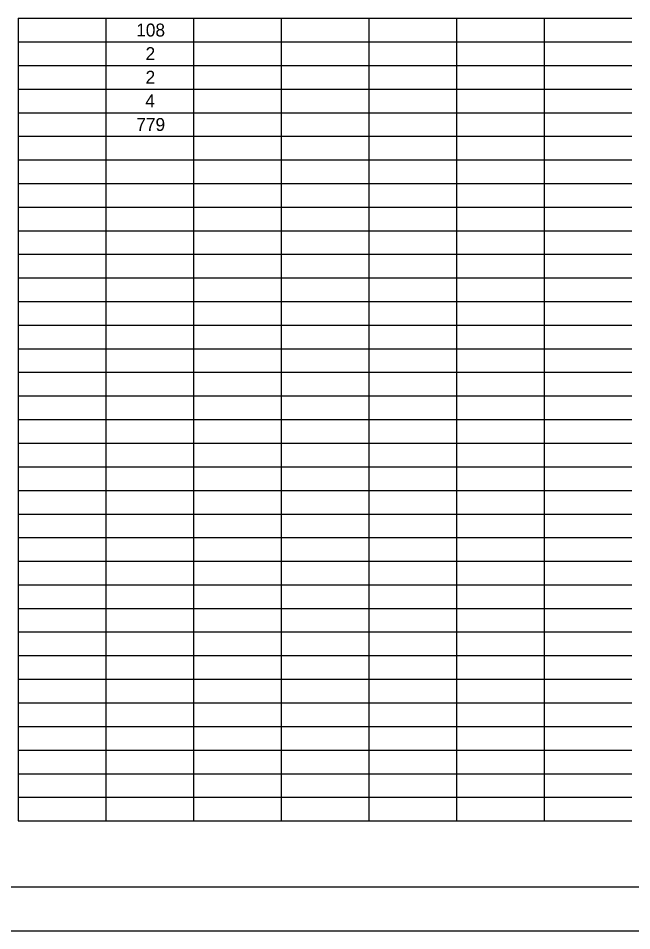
# Model space of a CAD drawing. Extents: x 0 to 34, y 0 to 22.
# Drawn here: x 8.52 to 15.54, y 0 to 10.43 of the extents above; entities that cross this region are included whole.
import ezdxf

# ---------------------------------------------------------------- set-up
doc = ezdxf.new("R2010")
doc.units = 0
for name, color, linetype in [('SH_Border', 7, 'Continuous'), ('SH_Cut_Line', 7, 'Continuous'), ('SH_Text', 7, 'Continuous')]:
    doc.layers.add(name, color=color, linetype=linetype)

msp = doc.modelspace()

# ---------------------------------------------------------------- linework, layer by layer
at = {"layer": 'SH_Border'}
msp.add_lwpolyline([(1.5, 21.5), (33.5, 21.5), (33.5, 0.5), (1.5, 0.5)], close=True, dxfattribs=at)
at = {"layer": 'SH_Cut_Line'}
msp.add_lwpolyline([(0, 0), (34, 0), (34, 22), (0, 22)], close=True, dxfattribs=at)
at = {"layer": 'SH_Text'}
for p, q in [((8.518, 10.434), (9.52, 10.434)), ((8.518, 10.434), (8.518, 10.164)), ((9.52, 10.434), (11.525, 10.434)), ((9.52, 10.434), (9.52, 10.164)), ((10.523, 10.434), (10.523, 10.164)), ((11.525, 10.434), (12.528, 10.434)), ((11.525, 10.434), (11.525, 10.164)), ((12.528, 10.434), (13.53, 10.434)), ((12.528, 10.434), (12.528, 10.164)), ((13.53, 10.434), (14.533, 10.434)), ((13.53, 10.434), (13.53, 10.164)), ((14.533, 10.434), (15.535, 10.434)), ((14.533, 10.434), (14.533, 10.164)), ((8.518, 10.164), (9.52, 10.164)), ((8.518, 10.164), (8.518, 9.354)), ((9.52, 10.164), (11.525, 10.164)), ((9.52, 10.164), (9.52, 9.354)), ((10.523, 10.164), (10.523, 9.354)), ((11.525, 10.164), (12.528, 10.164)), ((11.525, 10.164), (11.525, 9.354)), ((12.528, 10.164), (13.53, 10.164)), ((12.528, 10.164), (12.528, 9.354)), ((13.53, 10.164), (14.533, 10.164)), ((13.53, 10.164), (13.53, 9.354)), ((14.533, 10.164), (15.535, 10.164)), ((14.533, 10.164), (14.533, 9.354)), ((8.518, 9.894), (9.52, 9.894)), ((9.52, 9.894), (11.525, 9.894)), ((11.525, 9.894), (12.528, 9.894)), ((12.528, 9.894), (13.53, 9.894)), ((13.53, 9.894), (14.533, 9.894)), ((14.533, 9.894), (15.535, 9.894)), ((8.518, 9.624), (9.52, 9.624)), ((9.52, 9.624), (11.525, 9.624)), ((11.525, 9.624), (12.528, 9.624)), ((12.528, 9.624), (13.53, 9.624)), ((13.53, 9.624), (14.533, 9.624)), ((14.533, 9.624), (15.535, 9.624)), ((8.518, 9.354), (9.52, 9.354)), ((8.518, 9.354), (8.518, 8.814)), ((9.52, 9.354), (11.525, 9.354)), ((9.52, 9.354), (9.52, 8.814)), ((10.523, 9.354), (10.523, 8.814)), ((11.525, 9.354), (12.528, 9.354)), ((11.525, 9.354), (11.525, 8.814)), ((12.528, 9.354), (13.53, 9.354)), ((12.528, 9.354), (12.528, 8.814)), ((13.53, 9.354), (14.533, 9.354)), ((13.53, 9.354), (13.53, 8.814)), ((14.533, 9.354), (15.535, 9.354)), ((14.533, 9.354), (14.533, 8.814)), ((8.518, 9.084), (9.52, 9.084)), ((9.52, 9.084), (11.525, 9.084)), ((11.525, 9.084), (12.528, 9.084)), ((12.528, 9.084), (13.53, 9.084)), ((13.53, 9.084), (14.533, 9.084)), ((14.533, 9.084), (15.535, 9.084)), ((8.518, 8.814), (9.52, 8.814)), ((8.518, 8.814), (8.518, 8.004)), ((9.52, 8.814), (11.525, 8.814)), ((9.52, 8.814), (9.52, 8.004)), ((10.523, 8.814), (10.523, 8.004)), ((11.525, 8.814), (12.528, 8.814)), ((11.525, 8.814), (11.525, 8.004)), ((12.528, 8.814), (13.53, 8.814)), ((12.528, 8.814), (12.528, 8.004)), ((13.53, 8.814), (14.533, 8.814)), ((13.53, 8.814), (13.53, 8.004)), ((14.533, 8.814), (15.535, 8.814)), ((14.533, 8.814), (14.533, 8.004)), ((8.518, 8.544), (9.52, 8.544)), ((9.52, 8.544), (11.525, 8.544)), ((11.525, 8.544), (12.528, 8.544)), ((12.528, 8.544), (13.53, 8.544)), ((13.53, 8.544), (14.533, 8.544)), ((14.533, 8.544), (15.535, 8.544)), ((8.518, 8.274), (9.52, 8.274)), ((9.52, 8.274), (11.525, 8.274)), ((11.525, 8.274), (12.528, 8.274)), ((12.528, 8.274), (13.53, 8.274)), ((13.53, 8.274), (14.533, 8.274)), ((14.533, 8.274), (15.535, 8.274)), ((8.518, 8.004), (9.52, 8.004)), ((8.518, 8.004), (8.518, 7.465)), ((9.52, 8.004), (11.525, 8.004)), ((9.52, 8.004), (9.52, 7.465)), ((10.523, 8.004), (10.523, 7.465)), ((11.525, 8.004), (12.528, 8.004)), ((11.525, 8.004), (11.525, 7.465)), ((12.528, 8.004), (13.53, 8.004)), ((12.528, 8.004), (12.528, 7.465)), ((13.53, 8.004), (14.533, 8.004)), ((13.53, 8.004), (13.53, 7.465)), ((14.533, 8.004), (15.535, 8.004)), ((14.533, 8.004), (14.533, 7.465)), ((8.518, 7.735), (9.52, 7.735)), ((9.52, 7.735), (11.525, 7.735)), ((11.525, 7.735), (12.528, 7.735)), ((12.528, 7.735), (13.53, 7.735)), ((13.53, 7.735), (14.533, 7.735)), ((14.533, 7.735), (15.535, 7.735)), ((8.518, 7.465), (9.52, 7.465)), ((8.518, 7.465), (8.518, 6.655)), ((9.52, 7.465), (11.525, 7.465)), ((9.52, 7.465), (9.52, 6.655)), ((10.523, 7.465), (10.523, 6.655)), ((11.525, 7.465), (12.528, 7.465)), ((11.525, 7.465), (11.525, 6.655)), ((12.528, 7.465), (13.53, 7.465)), ((12.528, 7.465), (12.528, 6.655)), ((13.53, 7.465), (14.533, 7.465)), ((13.53, 7.465), (13.53, 6.655)), ((14.533, 7.465), (15.535, 7.465)), ((14.533, 7.465), (14.533, 6.655)), ((8.518, 7.195), (9.52, 7.195)), ((9.52, 7.195), (11.525, 7.195)), ((11.525, 7.195), (12.528, 7.195)), ((12.528, 7.195), (13.53, 7.195)), ((13.53, 7.195), (14.533, 7.195)), ((14.533, 7.195), (15.535, 7.195)), ((8.518, 6.925), (9.52, 6.925)), ((9.52, 6.925), (11.525, 6.925)), ((11.525, 6.925), (12.528, 6.925)), ((12.528, 6.925), (13.53, 6.925)), ((13.53, 6.925), (14.533, 6.925)), ((14.533, 6.925), (15.535, 6.925)), ((8.518, 6.655), (9.52, 6.655)), ((8.518, 6.655), (8.518, 5.575)), ((9.52, 6.655), (11.525, 6.655)), ((9.52, 6.655), (9.52, 5.575)), ((10.523, 6.655), (10.523, 5.575)), ((11.525, 6.655), (12.528, 6.655)), ((11.525, 6.655), (11.525, 5.575)), ((12.528, 6.655), (13.53, 6.655)), ((12.528, 6.655), (12.528, 5.575)), ((13.53, 6.655), (14.533, 6.655)), ((13.53, 6.655), (13.53, 5.575)), ((14.533, 6.655), (15.535, 6.655)), ((14.533, 6.655), (14.533, 5.575)), ((8.518, 6.385), (9.52, 6.385)), ((9.52, 6.385), (11.525, 6.385)), ((11.525, 6.385), (12.528, 6.385)), ((12.528, 6.385), (13.53, 6.385)), ((13.53, 6.385), (14.533, 6.385)), ((14.533, 6.385), (15.535, 6.385)), ((8.518, 6.115), (9.52, 6.115)), ((9.52, 6.115), (11.525, 6.115)), ((11.525, 6.115), (12.528, 6.115)), ((12.528, 6.115), (13.53, 6.115)), ((13.53, 6.115), (14.533, 6.115)), ((14.533, 6.115), (15.535, 6.115)), ((8.518, 5.845), (9.52, 5.845)), ((9.52, 5.845), (11.525, 5.845)), ((11.525, 5.845), (12.528, 5.845)), ((12.528, 5.845), (13.53, 5.845)), ((13.53, 5.845), (14.533, 5.845)), ((14.533, 5.845), (15.535, 5.845)), ((8.518, 5.575), (9.52, 5.575)), ((8.518, 5.575), (8.518, 5.305)), ((9.52, 5.575), (11.525, 5.575)), ((9.52, 5.575), (9.52, 5.305)), ((10.523, 5.575), (10.523, 5.305)), ((11.525, 5.575), (12.528, 5.575)), ((11.525, 5.575), (11.525, 5.305)), ((12.528, 5.575), (13.53, 5.575)), ((12.528, 5.575), (12.528, 5.305)), ((13.53, 5.575), (14.533, 5.575)), ((13.53, 5.575), (13.53, 5.305)), ((14.533, 5.575), (15.535, 5.575)), ((14.533, 5.575), (14.533, 5.305)), ((8.518, 5.305), (9.52, 5.305)), ((8.518, 5.305), (8.518, 4.226)), ((9.52, 5.305), (11.525, 5.305)), ((9.52, 5.305), (9.52, 4.226)), ((10.523, 5.305), (10.523, 4.226)), ((11.525, 5.305), (12.528, 5.305)), ((11.525, 5.305), (11.525, 4.226)), ((12.528, 5.305), (13.53, 5.305)), ((12.528, 5.305), (12.528, 4.226)), ((13.53, 5.305), (14.533, 5.305)), ((13.53, 5.305), (13.53, 4.226)), ((14.533, 5.305), (15.535, 5.305)), ((14.533, 5.305), (14.533, 4.226)), ((8.518, 5.035), (9.52, 5.035)), ((9.52, 5.035), (11.525, 5.035)), ((11.525, 5.035), (12.528, 5.035)), ((12.528, 5.035), (13.53, 5.035)), ((13.53, 5.035), (14.533, 5.035)), ((14.533, 5.035), (15.535, 5.035)), ((8.518, 4.765), (9.52, 4.765)), ((9.52, 4.765), (11.525, 4.765)), ((11.525, 4.765), (12.528, 4.765)), ((12.528, 4.765), (13.53, 4.765)), ((13.53, 4.765), (14.533, 4.765)), ((14.533, 4.765), (15.535, 4.765)), ((8.518, 4.496), (9.52, 4.496)), ((9.52, 4.496), (11.525, 4.496)), ((11.525, 4.496), (12.528, 4.496)), ((12.528, 4.496), (13.53, 4.496)), ((13.53, 4.496), (14.533, 4.496)), ((14.533, 4.496), (15.535, 4.496)), ((8.518, 4.226), (9.52, 4.226)), ((8.518, 4.226), (8.518, 3.956)), ((9.52, 4.226), (11.525, 4.226)), ((9.52, 4.226), (9.52, 3.956)), ((10.523, 4.226), (10.523, 3.956)), ((11.525, 4.226), (12.528, 4.226)), ((11.525, 4.226), (11.525, 3.956)), ((12.528, 4.226), (13.53, 4.226)), ((12.528, 4.226), (12.528, 3.956)), ((13.53, 4.226), (14.533, 4.226)), ((13.53, 4.226), (13.53, 3.956)), ((14.533, 4.226), (15.535, 4.226)), ((14.533, 4.226), (14.533, 3.956)), ((8.518, 3.956), (9.52, 3.956)), ((8.518, 3.956), (8.518, 2.876)), ((9.52, 3.956), (11.525, 3.956)), ((9.52, 3.956), (9.52, 2.876)), ((10.523, 3.956), (10.523, 2.876)), ((11.525, 3.956), (12.528, 3.956)), ((11.525, 3.956), (11.525, 2.876)), ((12.528, 3.956), (13.53, 3.956)), ((12.528, 3.956), (12.528, 2.876)), ((13.53, 3.956), (14.533, 3.956)), ((13.53, 3.956), (13.53, 2.876)), ((14.533, 3.956), (15.535, 3.956)), ((14.533, 3.956), (14.533, 2.876)), ((8.518, 3.686), (9.52, 3.686)), ((9.52, 3.686), (11.525, 3.686)), ((11.525, 3.686), (12.528, 3.686)), ((12.528, 3.686), (13.53, 3.686)), ((13.53, 3.686), (14.533, 3.686)), ((14.533, 3.686), (15.535, 3.686)), ((8.518, 3.416), (9.52, 3.416)), ((9.52, 3.416), (11.525, 3.416)), ((11.525, 3.416), (12.528, 3.416)), ((12.528, 3.416), (13.53, 3.416)), ((13.53, 3.416), (14.533, 3.416)), ((14.533, 3.416), (15.535, 3.416)), ((8.518, 3.146), (9.52, 3.146)), ((9.52, 3.146), (11.525, 3.146)), ((11.525, 3.146), (12.528, 3.146)), ((12.528, 3.146), (13.53, 3.146)), ((13.53, 3.146), (14.533, 3.146)), ((14.533, 3.146), (15.535, 3.146)), ((8.518, 2.876), (9.52, 2.876)), ((8.518, 2.876), (8.518, 2.606)), ((9.52, 2.876), (11.525, 2.876)), ((9.52, 2.876), (9.52, 2.606)), ((10.523, 2.876), (10.523, 2.606)), ((11.525, 2.876), (12.528, 2.876)), ((11.525, 2.876), (11.525, 2.606)), ((12.528, 2.876), (13.53, 2.876)), ((12.528, 2.876), (12.528, 2.606)), ((13.53, 2.876), (14.533, 2.876)), ((13.53, 2.876), (13.53, 2.606)), ((14.533, 2.876), (15.535, 2.876)), ((14.533, 2.876), (14.533, 2.606)), ((8.518, 2.606), (9.52, 2.606)), ((8.518, 2.606), (8.518, 1.527)), ((9.52, 2.606), (11.525, 2.606)), ((9.52, 2.606), (9.52, 1.527)), ((10.523, 2.606), (10.523, 1.527)), ((11.525, 2.606), (12.528, 2.606)), ((11.525, 2.606), (11.525, 1.527)), ((12.528, 2.606), (13.53, 2.606)), ((12.528, 2.606), (12.528, 1.527)), ((13.53, 2.606), (14.533, 2.606)), ((13.53, 2.606), (13.53, 1.527)), ((14.533, 2.606), (15.535, 2.606)), ((14.533, 2.606), (14.533, 1.527)), ((8.518, 2.336), (9.52, 2.336)), ((9.52, 2.336), (11.525, 2.336)), ((11.525, 2.336), (12.528, 2.336)), ((12.528, 2.336), (13.53, 2.336)), ((13.53, 2.336), (14.533, 2.336)), ((14.533, 2.336), (15.535, 2.336)), ((8.518, 2.066), (9.52, 2.066)), ((9.52, 2.066), (11.525, 2.066)), ((11.525, 2.066), (12.528, 2.066)), ((12.528, 2.066), (13.53, 2.066)), ((13.53, 2.066), (14.533, 2.066)), ((14.533, 2.066), (15.535, 2.066)), ((8.518, 1.796), (9.52, 1.796)), ((9.52, 1.796), (11.525, 1.796)), ((11.525, 1.796), (12.528, 1.796)), ((12.528, 1.796), (13.53, 1.796)), ((13.53, 1.796), (14.533, 1.796)), ((14.533, 1.796), (15.535, 1.796)), ((8.518, 1.527), (9.52, 1.527)), ((8.518, 1.527), (8.518, 1.257)), ((9.52, 1.527), (11.525, 1.527)), ((9.52, 1.527), (9.52, 1.257)), ((10.523, 1.527), (10.523, 1.257)), ((11.525, 1.527), (12.528, 1.527)), ((11.525, 1.527), (11.525, 1.257)), ((12.528, 1.527), (13.53, 1.527)), ((12.528, 1.527), (12.528, 1.257)), ((13.53, 1.527), (14.533, 1.527)), ((13.53, 1.527), (13.53, 1.257)), ((14.533, 1.527), (15.535, 1.527)), ((14.533, 1.527), (14.533, 1.257)), ((8.518, 1.257), (9.52, 1.257)), ((9.52, 1.257), (11.525, 1.257)), ((11.525, 1.257), (12.528, 1.257)), ((12.528, 1.257), (13.53, 1.257)), ((13.53, 1.257), (14.533, 1.257)), ((14.533, 1.257), (15.535, 1.257))]:
    msp.add_line(p, q, dxfattribs=at)

# ---------------------------------------------------------------- texts
for s, height, p in [('108', 0.1478, (9.867, 10.225)), ('2', 0.148, (9.974, 9.955)), ('2', 0.148, (9.974, 9.685)), ('4', 0.148, (9.971, 9.415)), ('779', 0.1478, (9.868, 9.145))]:
    msp.add_text(s, height=height, dxfattribs=at).set_placement(p)

doc.saveas('drawing.dxf')
